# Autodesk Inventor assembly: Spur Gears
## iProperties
Created: 2008-01
Part Number: Spur Gears
Document SubType Name: Assembly
Designer: eruiz-tagle
Mass: 1.54008 g
Surface Area: 2.673 cm^2
Volume: 0.196189 cm^3
Density: 7.85 g/cm^3
ClientObjectVersion: 1
Author: eruiz-tagle
